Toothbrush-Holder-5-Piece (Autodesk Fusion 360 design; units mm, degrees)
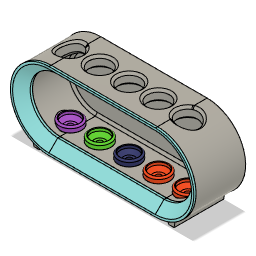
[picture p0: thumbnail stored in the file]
sketch "Sketch2" plane through (0, 0, 0) normal (0, 0, 1) x axis (1, 0, 0)
  line L1 (-28.3059, 111.8455) -> (-168.3059, 111.8455)
  line L2 (-28.3059, 41.8455) -> (-28.3059, 111.8455)
  line L3 (-168.3059, 41.8455) -> (-28.3059, 41.8455)
  line L4 (-168.3059, 111.8455) -> (-168.3059, 41.8455)
  circle C1 centre (-133.3059, 76.8455) radius 35
  circle C2 centre (-63.3059, 76.8455) radius 35
  point P2 (-168.3059, 111.8455)
  point P3 (-28.3059, 111.8455)
  point P5 (-168.3059, 41.8455)
  horizontal L1
  vertical L2
  horizontal L3
  vertical L4
  tangent L4 C1
  tangent L3 C1
  tangent L1 C1
  tangent L1 C2
  tangent L2 C2
  tangent L3 C2
  dimension "d6" distance P2 P3 = 140
  dimension "d7" distance P2 P5 = 70
extrude "Extrude2" new body sketch "Sketch2" profile of L1 L3 C1 C2 against normal blind 45
shell "Shell1" innerThickness 10
extrude "Extrude3" cut of existing geometry to an object offset -3
chamfer "Chamfer1" distance 8
sketch "Sketch3" plane through (0, 0, 0) normal (0, 0, 1) x axis (1, 0, 0)
  line L1 (-133.3059, 41.8455) -> (-63.3059, 41.8455)
  line L2 (-63.3059, 111.8455) -> (-133.3059, 111.8455)
  arc A1 centre (-63.3059, 76.8455) radius 35 clockwise from (-63.3059, 111.8455) to (-63.3059, 41.8455)
  arc A2 centre (-133.3059, 76.8455) radius 35 clockwise from (-133.3059, 41.8455) to (-133.3059, 111.8455)
extrude "Extrude4" sketch "Sketch3" to an object offset 2
combine "Combine1"
sketch "Sketch4" plane through (0, 0, -42) normal (0, 0, 1) x axis (1, 0, 0)
  line L1 (-63.3059, 51.8455) -> (-133.3059, 51.8455)
  line L2 (-133.3059, 101.8455) -> (-63.3059, 101.8455)
  arc A1 centre (-63.3059, 76.8455) radius 25 clockwise from (-63.3059, 101.8455) to (-63.3059, 51.8455)
  arc A2 centre (-133.3059, 76.8455) radius 25 clockwise from (-133.3059, 51.8455) to (-133.3059, 101.8455)
extrude "Extrude5" cut sketch "Sketch4" along normal blind 60
chamfer "Chamfer2" distance 8
offset_faces "OffsetFaces1" distance -0.1
sketch "Sketch5" plane through (0, 41.8455, 0) normal (0, -1, 0) x axis (1, 0, 0)
  line L1 (-133.3059, 0) -> (-63.3059, 0)
  line L2 (-133.3059, -45) -> (-133.3059, 0)
  line L3 (-63.3059, -45) -> (-133.3059, -45)
  line L4 (-63.3059, 0) -> (-63.3059, -45)
  line L5 (-63.3059, 0) -> (-28.3059, 0)
  line L6 (-63.3059, -45) -> (-63.3059, 0)
  line L7 (-28.3059, -45) -> (-63.3059, -45)
  line L8 (-63.3059, 0) -> (-63.3059, -45)
  line L9 (-168.3059, 0) -> (-133.3059, 0)
  line L10 (-133.3059, -45) -> (-133.3059, 0)
  line L11 (-133.3059, -45) -> (-168.3059, -45)
  line L12 (-133.3059, 0) -> (-133.3059, -45)
  line L13 (-168.3059, 0) -> (-28.3059, -45)
  line L14 (-48.3059, -22.5) -> (-148.3059, -22.5)
  line L15 (-28.3059, -45) -> (-28.3059, 0)
  circle C1 centre (-58.3059, -22.5) radius 10
  circle C2 centre (-84.9726, -22.5) radius 10
  circle C3 centre (-138.3059, -22.5) radius 10
  circle C4 centre (-111.6392, -22.5) radius 10
  point P11 (-168.3059, 0)
  point P14 (-168.3059, 0)
  point P9 (-28.3059, -45)
  point P15 (-28.3059, -45)
  point P17 (-28.3059, -45)
  point P6 (-28.3059, 0)
  point P20 (-28.3059, 0)
  point P18 (-58.3059, -22.5)
  point P19 (-48.3059, -22.5)
  point P21 (-84.9726, -22.5)
  point P22 (-138.3059, -22.5)
  point P16 (-148.3059, -22.5)
  point P23 (-111.6392, -22.5)
  coincident P11 P14
  coincident P9 P15
  perpendicular L6 L14
  midpoint L13 L14
  coincident P9 P17
  vertical L15
  coincident P6 P20
  coincident L14 P18
  coincident C1 P19
  coincident L14 P21
  coincident L14 P22
  coincident P16 C3
  coincident L14 P23
  dimension "d21" diameter C1 = 20
  dimension "d22" distance L15 P19 = 20
  dimension "d23" diameter C2 = 20
  dimension "d24" diameter C3 = 20
  dimension "d25" diameter C4 = 20
  dimension "d29" distance P18 P22 = 80
  dimension "d30" distance P18 P21 = 26.6667 (= "d29 / 3")
  dimension "d31" distance P21 P23 = 26.6667 (= "d29 / 3")
extrude "Extrude7" sketch "Sketch5" profile of C1 C2 C3 C4 to an object offset -3
chamfer "Chamfer3" distance 3
chamfer "Chamfer4" distance 2
extrude "Extrude8" sketch "Sketch5" profile of L2 L4 L6 L8 L10 L12 C1 C2 C3 C4 to an object offset 5
shell "Shell2" innerThickness 2
chamfer "Chamfer5" distance 3.15
fillet "Fillet1" radius 1.5
chamfer "Chamfer6" distance 0.5
chamfer "Chamfer7" distance 2
work_plane "WorkPlane1" AlongDistance -72
split "Split1"
move "Move4"
work_plane "WorkPlane2" AlongDistance -26.5
split "Split2"
copy_paste_bodies "CopyPasteBodies1"
move "Move5"
move "Move6"
copy_paste_bodies "CopyPasteBodies2"
move "Move7"
combine "Combine2"
combine "Combine3"
hole "Hole1" HoleDepth 8.188 HoleDiameter 5 TipAngle 118
hole "Hole2" HoleDepth 9 HoleDiameter 5 TipAngle 118
hole "Hole3" HoleDepth 9 HoleDiameter 5 TipAngle 118
hole "Hole4" HoleDepth 9 HoleDiameter 5 TipAngle 118
hole "Hole5" HoleDepth 9 HoleDiameter 5 TipAngle 118
sketch "Sketch8" plane through (0, 0, 0) normal (0, 0, 1) x axis (1, 0, 0)
  line L1 (-36.8059, 109.9869) -> (-133.3059, 109.9869)
  line L2 (-133.3059, 43.7041) -> (-36.8059, 43.7041)
  line L3 (-133.3059, 111.8455) -> (-36.8059, 111.8455)
  line L4 (-36.8059, 41.8455) -> (-133.3059, 41.8455)
  line L5 (-150.0319, 46.1007) -> (-148.9203, 40)
  line L6 (-142.8556, 43.1735) -> (-143.9203, 40)
  line L7 (-148.9203, 40) -> (-143.9203, 40)
  line L8 (-27.7692, 43.0322) -> (-26.7179, 40)
  line L9 (-21.7179, 40) -> (-26.7179, 40)
  line L10 (-20.7795, 45.7303) -> (-21.7179, 40)
  arc A1 centre (-36.8059, 76.8455) radius 33.1414 clockwise from (-36.8059, 109.9869) to (-36.8059, 43.7041)
  arc A2 centre (-133.3059, 76.8455) radius 33.1414 clockwise from (-133.3059, 43.7041) to (-133.3059, 109.9869)
  arc A3 centre (-133.3059, 76.8455) radius 35 clockwise from (-133.3059, 41.8455) to (-133.3059, 111.8455)
  arc A4 centre (-36.8059, 76.8455) radius 35 clockwise from (-36.8059, 111.8455) to (-36.8059, 41.8455)
  point P13 (-150.0319, 46.1007)
  point P15 (-142.8556, 43.1735)
  point P17 (-27.7692, 43.0322)
  point P19 (-20.7795, 45.7303)
  point P12 (-148.9203, 40)
  point P14 (-143.9203, 40)
  point P16 (-26.7179, 40)
  point P18 (-21.7179, 40)
  coincident A3 P13
  coincident A3 P15
  horizontal L7
  coincident A4 P17
  horizontal L9
  coincident A4 P19
  dimension "d87" distance P12 P14 = 5
  dimension "d88" distance P16 P18 = 5
extrude "Extrude11" add sketch "Sketch8" profile of A3 A4 L5 L6 L7 L8 L9 L10 against normal blind 45
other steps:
base_feature "Base Feature1"
base_feature "Base Feature2"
